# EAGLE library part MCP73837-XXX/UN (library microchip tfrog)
Battery charger MCP73837 Advanced Stand-Alone Li-Ion / Li-Polymer Battery Charge Management Controller with Autonomous AC-Adapter or USB-Port Source Selection Doc: http://www.microchip.com/wwwproducts/Devices.aspx?dDocName=en531507 Ref taken: MCP73837-FCI/UN
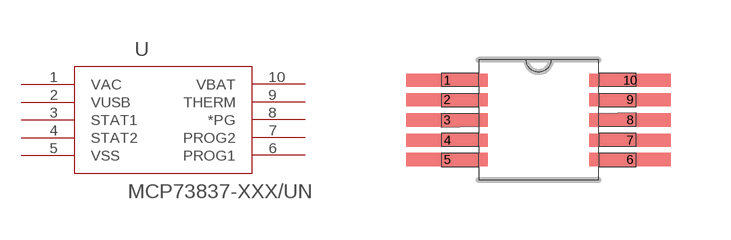
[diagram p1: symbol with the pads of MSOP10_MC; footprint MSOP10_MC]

Designator prefix -

## MCP73837-XXX/UN  [MSOP10_MC]
1  VAC  pas
2  VUSB  pas
3  STAT1  pas
4  STAT2  pas
5  VSS  pas
6  PROG1  pas
7  PROG2  pas
8  *PG  pas
9  THERM  pas
10  VBAT  pas

## Footprint MSOP10_MC (pad centres in mm)
MSOP10 with long pads (0.08inch instead of 0.06)
smd 2.032 x 0.33: 1 -2.286,0.991; 2 -2.286,0.508; 3 -2.286,0; 4 -2.286,-0.508; 5 -2.286,-0.991; 6 2.286,-0.991; 7 2.286,-0.508; 8 2.286,0; 9 2.286,0.508; 10 2.286,0.991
